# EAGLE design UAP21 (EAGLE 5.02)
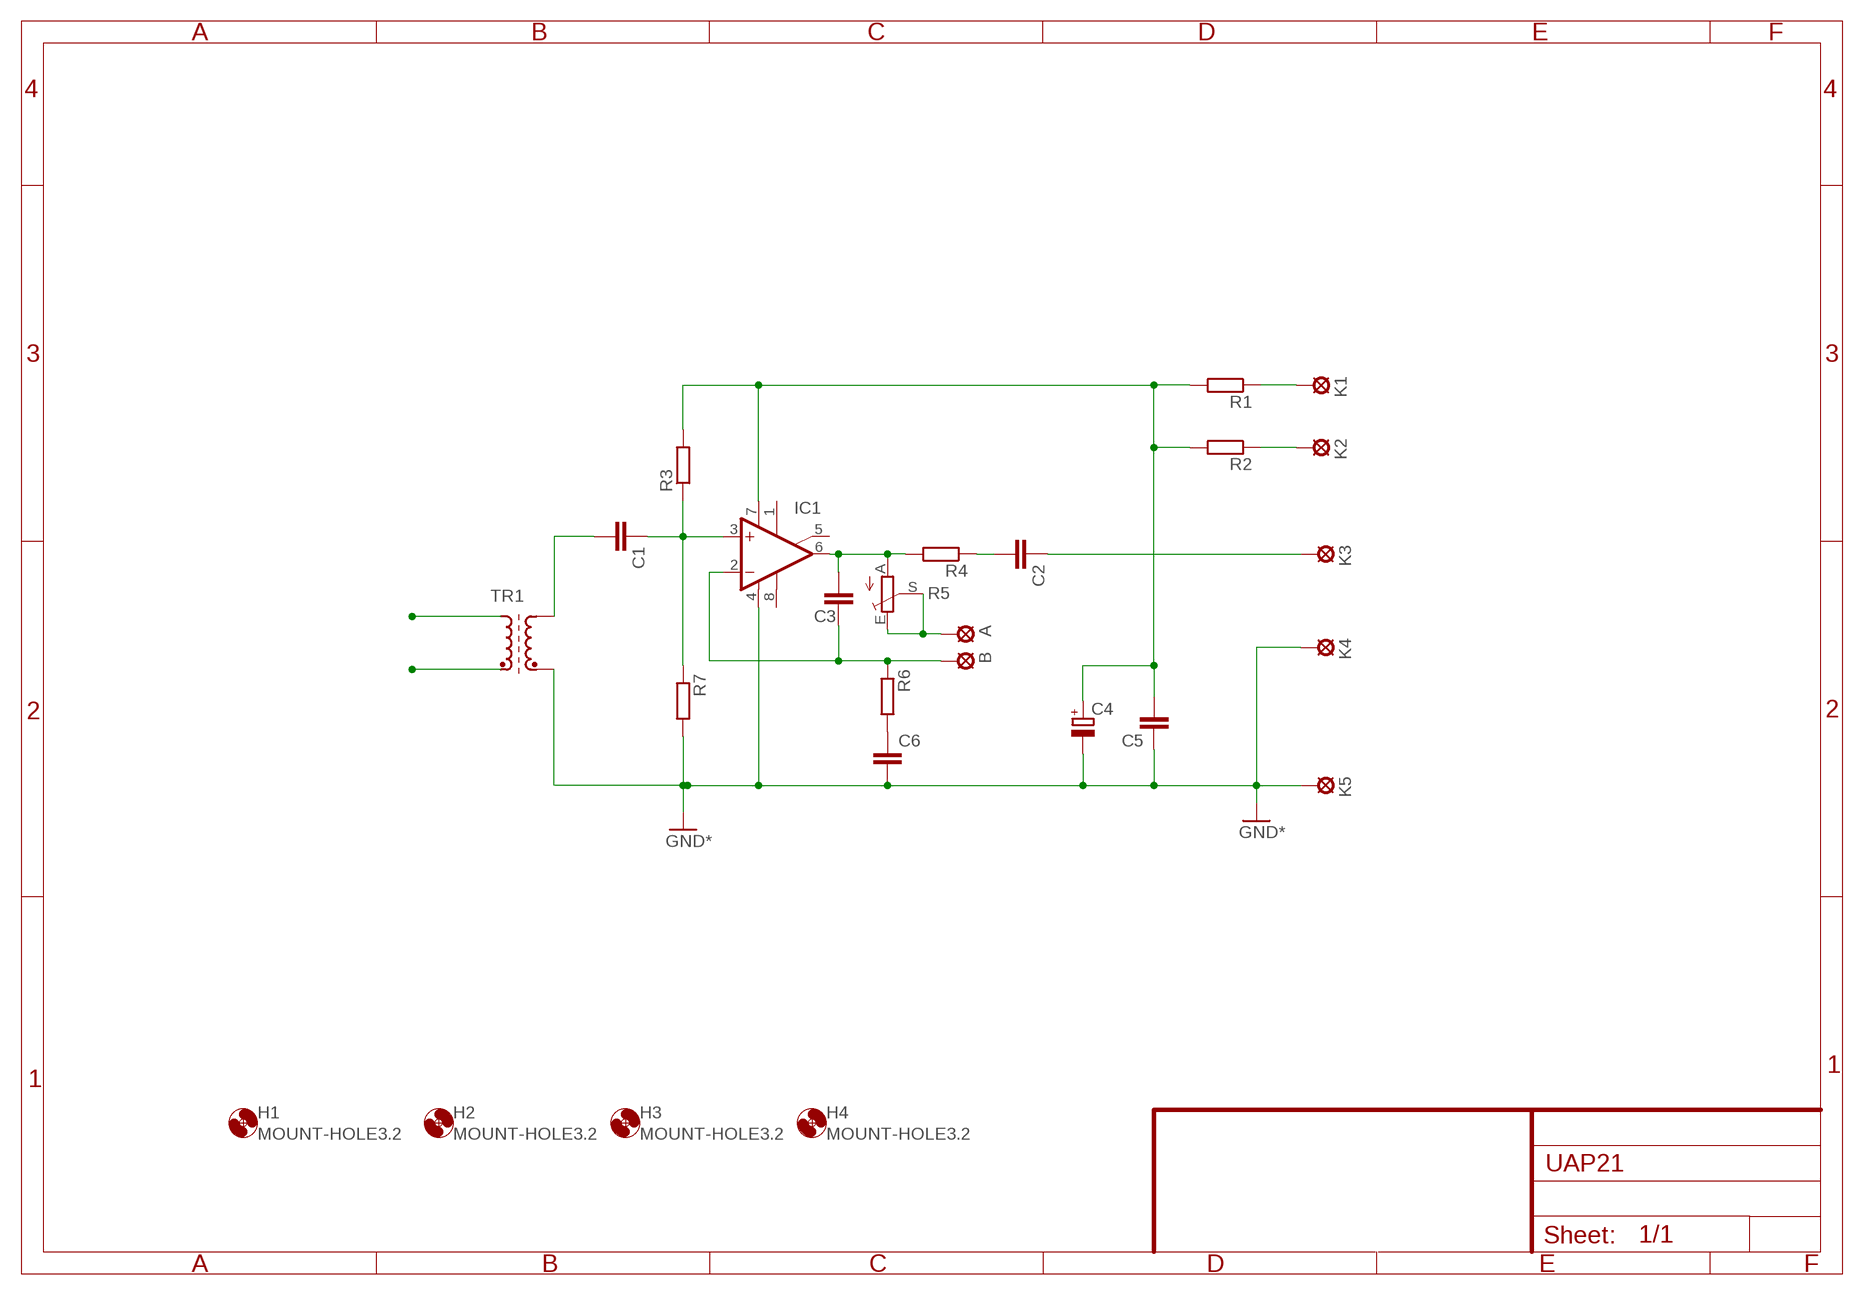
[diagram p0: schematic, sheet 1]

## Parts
A  LSP13  [LSP13]
B  LSP13  [LSP13]
C1  C-EU050-035X075  [C050-035X075]
C2  C-EU050-075X075  [C050-075X075]
C3  C-EU050-035X075  [C050-035X075]
C4  CPOL-EUE3.5-8  [E3,5-8]
C5  C-EU050-035X075  [C050-035X075]
C6  C-EU050-075X075  [C050-075X075]
H1  MOUNT-HOLE3.2  [3,2]
H2  MOUNT-HOLE3.2  [3,2]
H3  MOUNT-HOLE3.2  [3,2]
H4  MOUNT-HOLE3.2  [3,2]
IC1  uA741P  [DIL08]
K1  LSP13  [LSP13]
K2  LSP13  [LSP13]
K3  LSP13  [LSP13]
K4  LSP13  [LSP13]
K5  LSP13  [LSP13]
R1  R-EU_0207/10E  [0207/10E]
R2  R-EU_0207/10E  [0207/10E]
R3  R-EU_0207/10E  [0207/10E]
R4  R-EU_0207/10E  [0207/10E]
R5  TRIM_EU-B64Y  [B64Y]
R6  R-EU_0207/10E  [0207/10E]
R7  R-EU_0207/10E  [0207/10E]
TR1  RK25MOD  [ED25MOD]

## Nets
GND: C4.- C5.2 C6.1 IC1.4(V-) K4.MP K5.MP R7.2 TR1.4(S2) ; supply symbol labelled GND*
N$1: C1.1 TR1.3(S1)
N$2: C6.2 R6.2
N$5: C1.2 IC1.3(+IN) R3.1 R7.1
N$6: C2.2 K3.MP
N$7: K1.MP R1.1
N$8: C3.2 IC1.6(OUT) R4.2 R5.A
N$9: C2.1 R4.1
N$10: B.MP C3.1 IC1.2(-IN) R6.1
N$11: C4.+ C5.1 IC1.7(V+) R1.2 R2.2 R3.2
N$12: K2.MP R2.1
N$13: A.MP R5.E R5.S
Unconnected: IC1.1(ON1) IC1.5(ON2) IC1.8(OPT)

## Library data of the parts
A B K1-K5 = solpad:LSP13: SOLDER PAD
C1-C3 C5 C6 = rcl:C-EU: CAPACITOR, European symbol
C4 = rcl:CPOL-EU: POLARIZED CAPACITOR, European symbol
H1-H4 = holes:MOUNT-HOLE: MOUNTING HOLE with drill center marker
IC1 = linear:*741P: OP AMP
R1-R4 R6 R7 = rcl:R-EU_: RESISTOR, European symbol
R5 = pot:TRIM_EU-: POTENTIOMETER
TR1 = FMW:RK25MOD

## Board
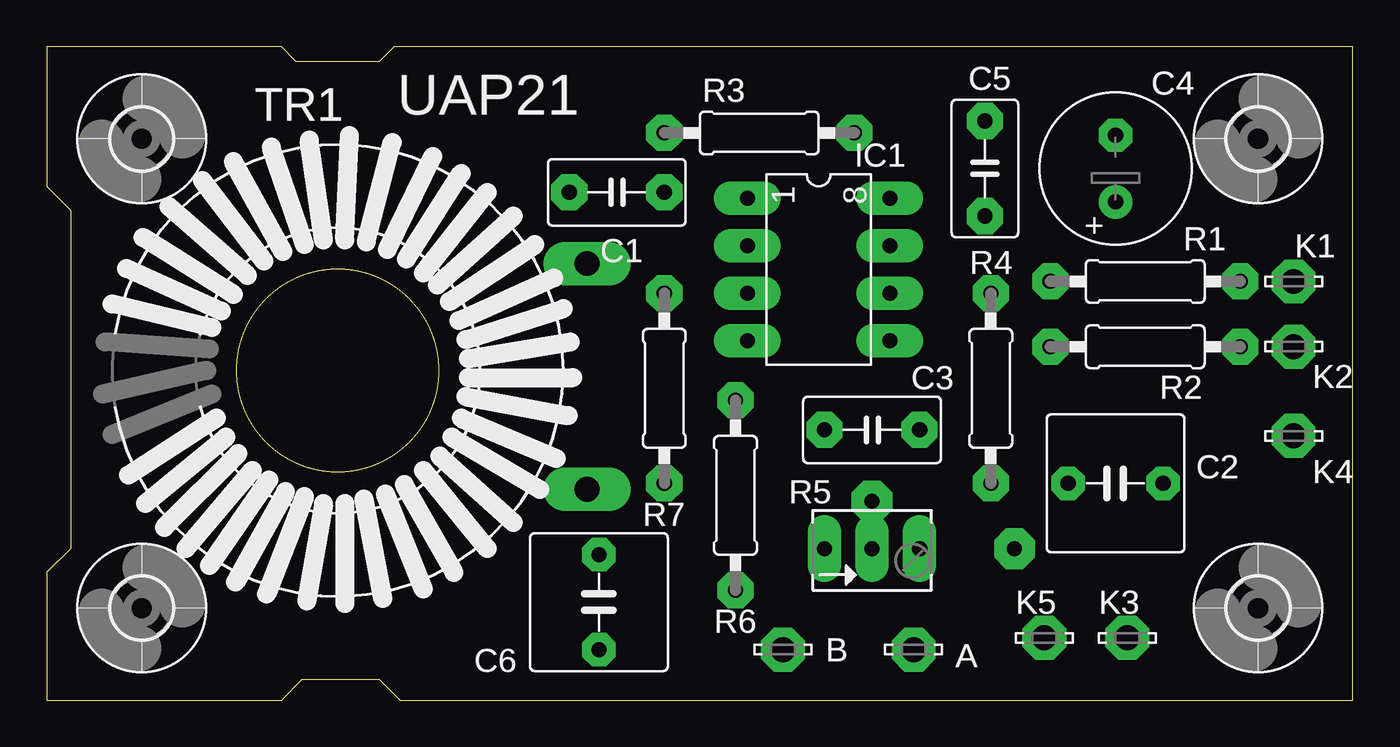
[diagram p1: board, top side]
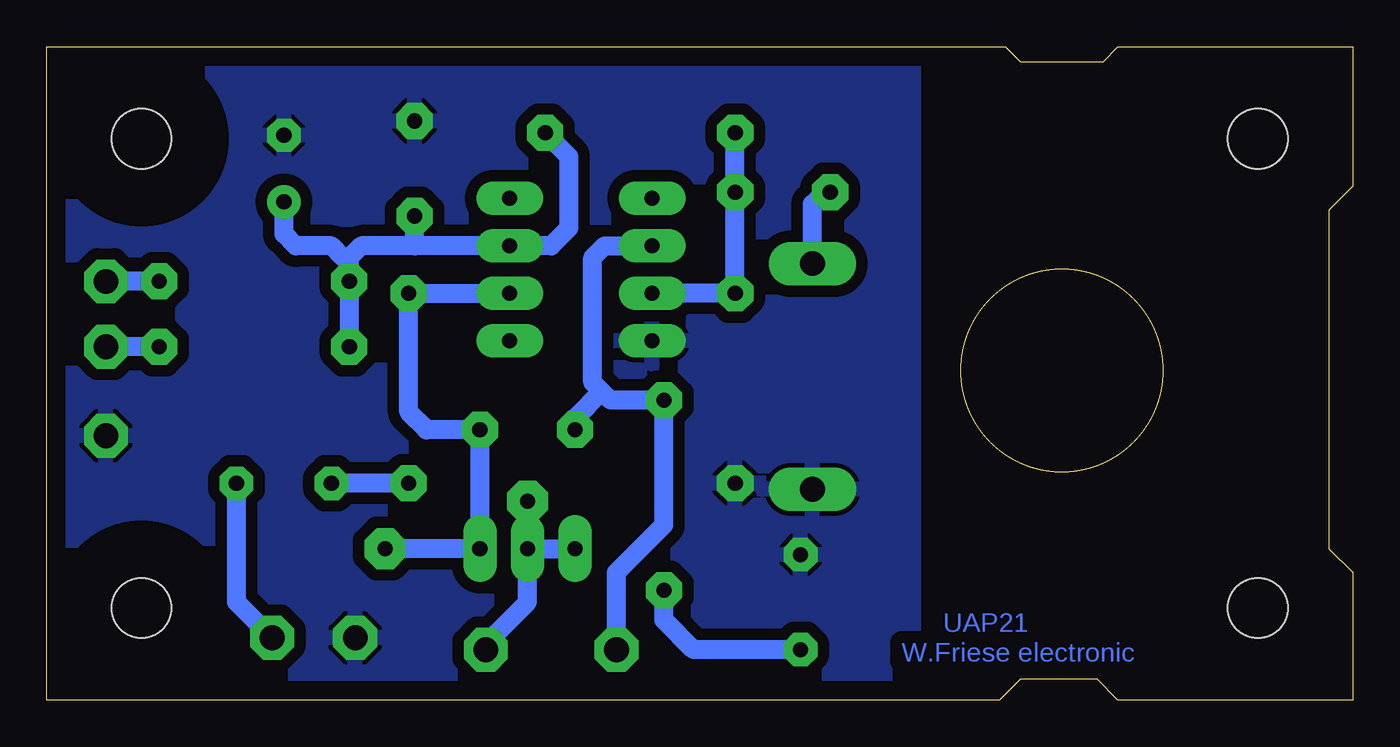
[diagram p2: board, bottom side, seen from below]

Size 69.83 x 34.92 mm. Coordinates in mm from the lower left corner, seen from the top.
Outline: 0.01,0.01 12.55,0.01 13.65,1.11 17.78,1.11 18.89,0 69.83,0.01 69.83,34.92 18.57,34.93 17.78,34.13 13.34,34.13 12.55,34.92 0.01,34.92 0.01,27.46 1.27,26.19 1.27,8.1 0,6.83 0.01,0.01
Outline: circle at 15.56,17.62 radius 5.41
Copper layers (1*16): Top 0.035mm / dielectric 1.5mm / Bottom 0.035mm
Design rules "default": minimum track width 10mil, minimum drill 24mil, track to track 8mil, track to pad 8mil, pad to pad 8mil, via to via 8mil, smd to smd 8mil, copper to edge 40mil, drill to drill 8mil, minimum pad ring 10mil, minimum via ring 8mil, stop-mask expansion 4mil, vias tented up to drill 0mil, thermal gap 10mil

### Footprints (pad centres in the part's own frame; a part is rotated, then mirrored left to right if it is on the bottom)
LSP13 = drill 1.321 pad 2.159 octagon: MP 0,0
C050-035X075 = drill 0.813 pad 1.93 octagon: 1 -2.54,0; 2 2.54,0
C050-075X075 = drill 0.813 octagon: 1 -2.54,0; 2 2.54,0
E3,5-8 = drill 0.813 pad 1.6 round: + -1.778,0 | drill 0.813 pad 1.6 octagon: - 1.778,0
3,2 = hole 3.2: 0,0
DIL08 = drill 0.813 long: 1 -3.81,-3.81; 2 -1.27,-3.81; 3 1.27,-3.81; 4 3.81,-3.81; 5 3.81,3.81; 6 1.27,3.81; 7 -1.27,3.81; 8 -3.81,3.81
0207/10E = drill 0.813 pad 1.93 octagon: 1 -4.445,0; 2 5.715,0
B64Y = drill 0.813 long: A 2.54,0; E -2.54,0; S 0,0
ED25MOD = drill 1.321 long: 3 13.335,5.715; 4 13.335,-6.35

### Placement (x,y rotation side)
A  46.35,2.7 180 top
B  39.37,2.7 0 top
C1  30.48,27.15 0 top
C2  57.15,11.59 0 top
C3  44.13,14.45 0 top
C4  57.15,28.42 90 top
C5  50.16,28.42 90 top
C6  29.53,5.24 270 top
H1  5.08,4.92 0 top
H2  64.77,4.92 0 top
H3  64.77,30 0 top
H4  5.08,30 0 top
IC1  41.27,23.02 270 top
K1  66.67,22.38 0 top
K2  66.67,18.89 0 top
K3  57.78,3.33 0 top
K4  66.67,14.13 0 top
K5  53.34,3.33 0 top
R1  59.37,22.38 180 top
R2  59.37,18.89 180 top
R3  37.47,30.32 0 top
R4  50.48,16.03 90 top
R5  44.13,8.1 0 top
R6  36.83,11.59 270 top
R7  33.02,17.3 270 top
TR1  15.56,17.62 0 top

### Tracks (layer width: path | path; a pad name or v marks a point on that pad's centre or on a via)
GND
  pour Bottom (isolate 0.61): 23.5,34.45 23.5,0.48 69.22,0.48 69.22,34.45
N$1
  Bottom 1.016: C1.1 28.26,27.15 28.89,26.51 TR1.3
N$2
  Bottom 1.016: R6.2 36.83,4.29 35.24,2.7 C6.2
N$5
  Bottom 1.016: IC1.3 R7.1 C1.2 R3.1
N$6
  Bottom 1.016: C2.2 59.69,5.24 K3.MP
N$7
  Bottom 1.016: R1.1 K1.MP
N$8  (via drill 0.8 pad 2.18)
  Bottom 1.016: IC1.6 R4.2 50.48,15.4 49.53,14.45 C3.2 R5.A v51.75,8.1
N$9
  Bottom 1.016: R4.1 C2.1
N$10
  Bottom 1.016: IC1.2 40.01,24.29 40.64,23.65 40.64,16.99 40.16,16.51 | 40.16,16.51 39.69,16.03 R6.1 36.83,9.37 39.37,6.83 B.MP | 40.16,16.51 | C3.1 41.59,15.08 40.16,16.51
N$11
  Bottom 1.016: 50.16,24.29 IC1.7 42.86,24.29 41.91,25.24 41.91,29.05 R3.2 | 50.16,24.29 53.02,24.29 53.66,23.65 | 53.66,23.65 R1.2 R2.2 | 50.16,24.29 C5.1 | 53.66,23.65 53.98,23.65 54.61,24.29 56.52,24.29 57.15,24.92 C4.+
N$12
  Bottom 1.016: R2.1 K2.MP
N$13  (via drill 0.8 pad 2.18)
  Bottom 1.016: R5.S R5.E | R5.S 44.13,5.24 46.35,3.02 A.MP | R5.S v44.13,10.64

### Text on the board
Bottom: UAP21 | W.Friese electronic
tPlace: UAP21
_tNames: C5 | C4 | R3 | TR1 | IC1 | C1 | R1 | R4 | K1 | R2 | C3 | K2 | C2 | K4 | R5 | R7 | K5 | K3 | R6 | A | C6 | B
